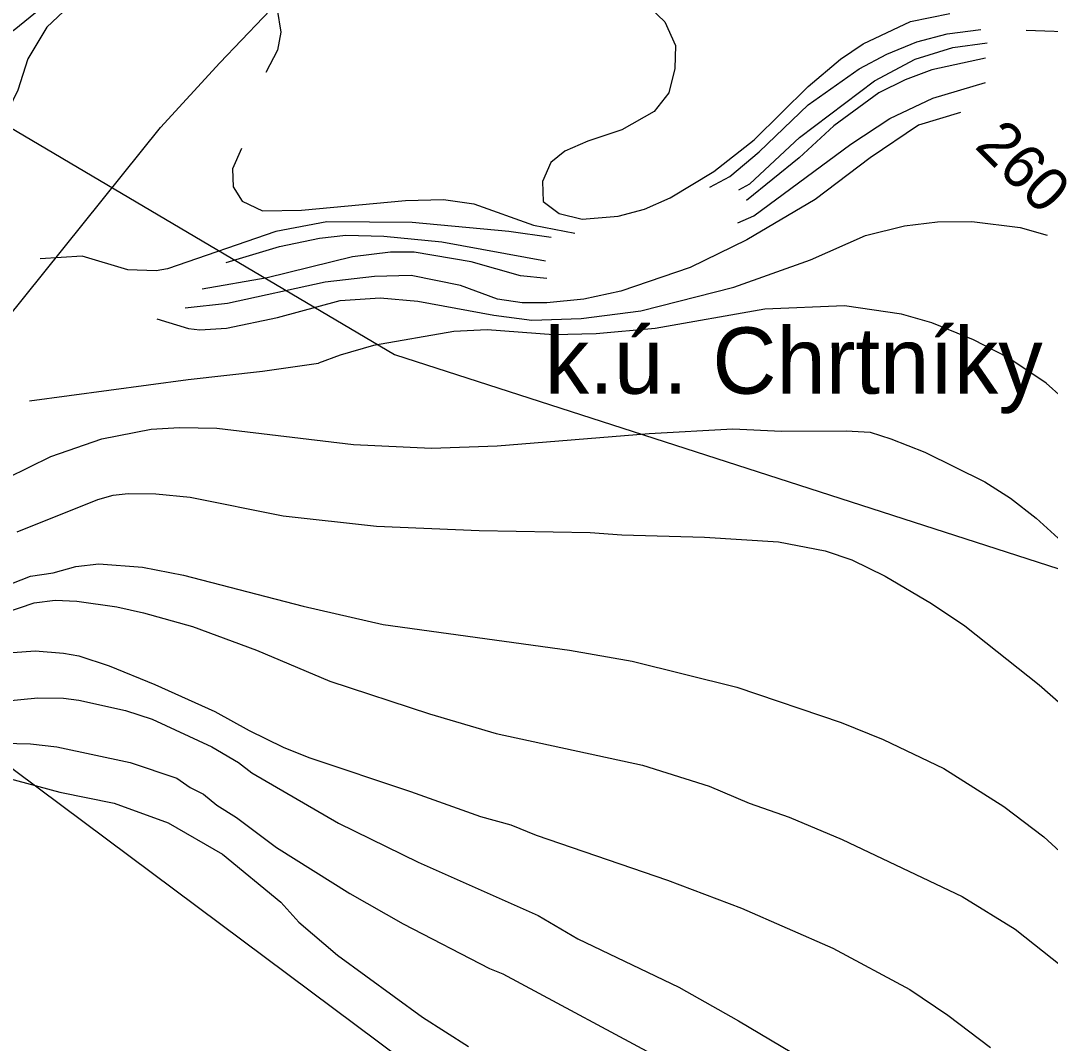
# Model space of a CAD drawing. Extents: x -662620 to -656370, y -1067090 to -1062990.
# Drawn here: x -660377.1 to -660066.6, y -1065930.1 to -1065621.6 of the extents above; entities that cross this region are included whole.
import ezdxf

# ---------------------------------------------------------------- set-up
doc = ezdxf.new("R2010")
doc.units = 0
for name, color, linetype in [('CHRANENE_LOZISKOVE_UZEMI', 7, 'Continuous'), ('NÁZEV_K__Ú_', 7, 'Continuous'), ('Ochr__pás__vod__zdroje_II__stupně', 7, 'Continuous'), ('SILNICE_II__TŘÍDY_A_III__TŘÍDY', 7, 'Continuous'), ('VRSTEVNICE_ZDŮRAZNĚNÁ', 7, 'Continuous'), ('VRSTEVNICE_ZDŮRAZNĚNÁ_-_POPIS', 7, 'Continuous'), ('VRSTEVNICE_ZÁKLADNÍ', 7, 'Continuous')]:
    doc.layers.add(name, color=color, linetype=linetype)

msp = doc.modelspace()

# ---------------------------------------------------------------- linework, layer by layer
at = {"layer": 'CHRANENE_LOZISKOVE_UZEMI'}
msp.add_lwpolyline([(-660732.31, -1065445.66), (-660264.34, -1065722.38), (-659885.89, -1065844.46), (-659943.47, -1066017.32)], dxfattribs=at)
at = {"layer": 'Ochr__pás__vod__zdroje_II__stupně'}
msp.add_lwpolyline([(-659772.42, -1066554.14), (-659800.07, -1066551.37), (-659811.95, -1066548.99), (-659926.01, -1066408.79), (-660023.43, -1066204.43), (-660077.21, -1066064.42), (-660108.05, -1066028.84), (-660146.01, -1066021.72), (-660474.51, -1065776.5), (-660482.87, -1065770.25), (-660599.12, -1065701.46), (-660658.43, -1065661.13), (-660656.42, -1065640.1), (-660662.94, -1065633.72), (-660669.94, -1065617.13), (-660675.36, -1065567.65)], dxfattribs=at)
at = {"layer": 'SILNICE_II__TŘÍDY_A_III__TŘÍDY'}
msp.add_lwpolyline([(-660468.75, -1065994.7), (-660462.97, -1065827.16), (-660446.28, -1065792.5), (-660334.88, -1065653.89), (-660317.01, -1065634.42), (-660277.86, -1065593.29), (-660232.35, -1065571.59), (-660040.54, -1065499.48), (-660012.53, -1065477.78), (-659990.24, -1065445.75), (-659930.63, -1065272.66), (-659916.62, -1065191.45)], dxfattribs=at)
at = {"layer": 'VRSTEVNICE_ZDŮRAZNĚNÁ'}
for points in [[(-660189.39, -1065615.74), (-660182.81, -1065622.03), (-660179.67, -1065629.18), (-660179.81, -1065636.04), (-660181.67, -1065643.47), (-660186.1, -1065649.05), (-660195.82, -1065654.62), (-660206.11, -1065658.05), (-660212.97, -1065661.05), (-660217.26, -1065664.48), (-660219.69, -1065670.2), (-660219.54, -1065676.2), (-660214.69, -1065679.78), (-660207.82, -1065681.49), (-660196.96, -1065680.63), (-660188.96, -1065678.49), (-660181.24, -1065675.06), (-660168.09, -1065667.2), (-660155.94, -1065657.62), (-660139.65, -1065641.47), (-660129.93, -1065633.32), (-660123.06, -1065628.61), (-660108.77, -1065621.89), (-660096.91, -1065619.46)], [(-660093.67, -1065649.31), (-660106.33, -1065653.19), (-660120.92, -1065663.05), (-660137.5, -1065675.63), (-660158.08, -1065687.78), (-660175.24, -1065696.07), (-660196.1, -1065703.22), (-660207.25, -1065705.65), (-660218.4, -1065706.79), (-660225.83, -1065706.79), (-660233.27, -1065705.65), (-660244.42, -1065701.5), (-660259.28, -1065698.5), (-660270.43, -1065698.79), (-660285.29, -1065700.5), (-660314.74, -1065706.93), (-660327.46, -1065708.36)], [(-660425.64, -1065809.51), (-660407.67, -1065801.78), (-660401.08, -1065799.78), (-660374.14, -1065789.17), (-660367.26, -1065788.17), (-660360.38, -1065786.3), (-660353.5, -1065785.44), (-660340.31, -1065786.45), (-660327.99, -1065788.88), (-660291.87, -1065798.2), (-660267.8, -1065803.79), (-660211.61, -1065811.53), (-660192.7, -1065814.83), (-660161.17, -1065822.71), (-660129.64, -1065833.31), (-660117.03, -1065838.47), (-660098.68, -1065847.21), (-660080.62, -1065858.68), (-660068.59, -1065867.85), (-660049.24, -1065885.48), (-660038.49, -1065898.81), (-660033.04, -1065907.26), (-660022.15, -1065929.05), (-660001.51, -1065962.01)], [(-660419.87, -1065848.7), (-660406.15, -1065849.41), (-660393.63, -1065848.65), (-660387.61, -1065848.79), (-660381.59, -1065849.94), (-660365.25, -1065854.38), (-660348.91, -1065857.68), (-660332.57, -1065863.55), (-660316.24, -1065873.01), (-660298.61, -1065887.49), (-660293.16, -1065893.51), (-660281.55, -1065903.54), (-660255.9, -1065922.17), (-660242, -1065931.05)]]:
    msp.add_lwpolyline(points, dxfattribs=at)
at = {"layer": 'VRSTEVNICE_ZÁKLADNÍ'}
for points in [[(-660440.08, -1065706.23), (-660427.51, -1065691.78), (-660420.22, -1065682.06), (-660417.08, -1065676.06), (-660417.08, -1065671.2), (-660421.79, -1065661.77), (-660422.22, -1065658.34), (-660420.08, -1065652.62), (-660417.94, -1065650.05), (-660413.08, -1065646.04), (-660379.06, -1065624.46), (-660366.19, -1065613.88), (-660331.75, -1065582.44), (-660320.17, -1065572.72), (-660298.46, -1065557.93), (-660282.72, -1065548.85), (-660243.27, -1065528.98), (-660222.4, -1065519.69), (-660195.25, -1065508.83), (-660183.81, -1065503.4), (-660176.24, -1065497.25), (-660175.29, -1065489.85)], [(-660440.08, -1065706.23), (-660427.51, -1065691.78), (-660420.22, -1065682.06), (-660417.08, -1065676.06), (-660417.08, -1065671.2), (-660421.79, -1065661.77), (-660422.22, -1065658.34), (-660420.08, -1065652.62), (-660417.94, -1065650.05), (-660413.08, -1065646.04), (-660379.06, -1065624.46), (-660366.19, -1065613.88), (-660331.75, -1065582.44), (-660320.17, -1065572.72), (-660298.46, -1065557.93), (-660282.72, -1065548.85), (-660243.27, -1065528.98), (-660222.4, -1065519.69), (-660195.25, -1065508.83), (-660183.81, -1065503.4), (-660176.24, -1065497.25), (-660175.29, -1065489.85)], [(-660159.71, -1065490.21), (-660160.08, -1065500.11), (-660166.95, -1065505.97), (-660171.09, -1065508.4), (-660188.24, -1065516.12), (-660207.54, -1065523.12), (-660234.12, -1065533.84), (-660269, -1065549.85), (-660292.44, -1065562.57), (-660306.45, -1065571.72), (-660322.74, -1065584.58), (-660335.18, -1065596.59), (-660362.48, -1065617.32), (-660369.2, -1065623.6), (-660374.91, -1065633.18), (-660377.91, -1065642.61), (-660382.49, -1065652.19), (-660388.63, -1065659.77), (-660397.64, -1065667.48), (-660406.36, -1065676.2), (-660416.08, -1065687.35), (-660423.64, -1065697.23), (-660429.13, -1065707.57)], [(-660159.71, -1065490.21), (-660160.08, -1065500.11), (-660166.95, -1065505.97), (-660171.09, -1065508.4), (-660188.24, -1065516.12), (-660207.54, -1065523.12), (-660234.12, -1065533.84), (-660269, -1065549.85), (-660292.44, -1065562.57), (-660306.45, -1065571.72), (-660322.74, -1065584.58), (-660335.18, -1065596.59), (-660362.48, -1065617.32), (-660369.2, -1065623.6), (-660374.91, -1065633.18), (-660377.91, -1065642.61), (-660382.49, -1065652.19), (-660388.63, -1065659.77), (-660397.64, -1065667.48), (-660406.36, -1065676.2), (-660416.08, -1065687.35), (-660423.64, -1065697.23), (-660429.13, -1065707.57)], [(-660181.24, -1065523.55), (-660216.4, -1065535.41), (-660243.84, -1065547.14), (-660259.28, -1065554.71), (-660271.29, -1065561.57), (-660302.16, -1065582.44), (-660307.16, -1065589.44), (-660308.16, -1065593.02), (-660308.3, -1065597.73), (-660305.02, -1065608.02), (-660299.73, -1065618.32), (-660298.59, -1065625.18), (-660299.59, -1065630.61), (-660303.16, -1065637.33)], [(-660181.24, -1065523.55), (-660216.4, -1065535.41), (-660243.84, -1065547.14), (-660259.28, -1065554.71), (-660271.29, -1065561.57), (-660302.16, -1065582.44), (-660307.16, -1065589.44), (-660308.16, -1065593.02), (-660308.3, -1065597.73), (-660305.02, -1065608.02), (-660299.73, -1065618.32), (-660298.59, -1065625.18), (-660299.59, -1065630.61), (-660303.16, -1065637.33)], [(-660073.95, -1065624.5), (-660056.89, -1065625.18), (-660046.88, -1065626.46), (-660037.73, -1065628.75), (-660032.02, -1065631.32), (-660020.87, -1065629.04), (-660016.58, -1065629.75), (-660007.43, -1065633.75), (-660000.86, -1065633.75), (-659994.85, -1065631.89), (-659986.28, -1065627.75), (-659980.28, -1065624.03), (-659975.13, -1065619.6)], [(-660073.95, -1065624.5), (-660056.89, -1065625.18), (-660046.88, -1065626.46), (-660037.73, -1065628.75), (-660032.02, -1065631.32), (-660020.87, -1065629.04), (-660016.58, -1065629.75), (-660007.43, -1065633.75), (-660000.86, -1065633.75), (-659994.85, -1065631.89), (-659986.28, -1065627.75), (-659980.28, -1065624.03), (-659975.13, -1065619.6)], [(-660169.23, -1065671.89), (-660163.23, -1065668.63), (-660154.37, -1065661.2), (-660139.65, -1065647.05), (-660124.21, -1065636.18), (-660115.92, -1065631.75), (-660106.91, -1065628.04), (-660097.76, -1065625.61), (-660087.62, -1065624.32)], [(-660169.23, -1065671.89), (-660163.23, -1065668.63), (-660154.37, -1065661.2), (-660139.65, -1065647.05), (-660124.21, -1065636.18), (-660115.92, -1065631.75), (-660106.91, -1065628.04), (-660097.76, -1065625.61), (-660087.62, -1065624.32)], [(-660160.51, -1065672.68), (-660157.23, -1065670.91), (-660142.22, -1065656.91), (-660119.63, -1065639.76), (-660107.34, -1065633.32), (-660096.05, -1065629.75), (-660085.62, -1065628.32)], [(-660160.51, -1065672.68), (-660157.23, -1065670.91), (-660142.22, -1065656.91), (-660119.63, -1065639.76), (-660107.34, -1065633.32), (-660096.05, -1065629.75), (-660085.62, -1065628.32)], [(-660086.21, -1065632.97), (-660102.34, -1065636.47), (-660110.34, -1065639.47), (-660118.35, -1065643.47), (-660131.93, -1065653.33), (-660142.36, -1065663.05), (-660158.23, -1065675.92)], [(-660086.21, -1065632.97), (-660102.34, -1065636.47), (-660110.34, -1065639.47), (-660118.35, -1065643.47), (-660131.93, -1065653.33), (-660142.36, -1065663.05), (-660158.23, -1065675.92)], [(-660160.8, -1065682.61), (-660156.05, -1065680.56), (-660126.78, -1065658.91), (-660115.06, -1065651.19), (-660102.05, -1065645.04), (-660086.19, -1065640.33)], [(-660160.8, -1065682.61), (-660156.05, -1065680.56), (-660126.78, -1065658.91), (-660115.06, -1065651.19), (-660102.05, -1065645.04), (-660086.19, -1065640.33)], [(-660310.49, -1065660.18), (-660313.17, -1065666.34), (-660313.02, -1065671.77), (-660310.31, -1065676.06), (-660304.16, -1065679.06), (-660292.44, -1065678.78), (-660261, -1065675.92), (-660249.56, -1065675.63), (-660240.41, -1065676.92), (-660222.4, -1065683.35), (-660209.97, -1065685.78)], [(-660310.49, -1065660.18), (-660313.17, -1065666.34), (-660313.02, -1065671.77), (-660310.31, -1065676.06), (-660304.16, -1065679.06), (-660292.44, -1065678.78), (-660261, -1065675.92), (-660249.56, -1065675.63), (-660240.41, -1065676.92), (-660222.4, -1065683.35), (-660209.97, -1065685.78)], [(-660217.1, -1065687.08), (-660229.84, -1065685.21), (-660258.99, -1065682.49), (-660284.72, -1065682.35), (-660300.16, -1065685.21), (-660332.75, -1065696.5), (-660336.18, -1065697.07), (-660344.75, -1065696.79), (-660358.48, -1065692.64), (-660371.2, -1065693.5)], [(-660217.1, -1065687.08), (-660229.84, -1065685.21), (-660258.99, -1065682.49), (-660284.72, -1065682.35), (-660300.16, -1065685.21), (-660332.75, -1065696.5), (-660336.18, -1065697.07), (-660344.75, -1065696.79), (-660358.48, -1065692.64), (-660371.2, -1065693.5)], [(-660335.98, -1065711.57), (-660326.46, -1065714.51), (-660323.03, -1065714.94), (-660315.02, -1065714.37), (-660299.59, -1065711.22), (-660280.72, -1065706.08), (-660268.71, -1065705.22), (-660257.28, -1065706.22), (-660234.41, -1065710.51), (-660222.97, -1065711.94), (-660208.11, -1065711.51), (-660190.1, -1065709.22), (-660162.09, -1065702.07), (-660138.93, -1065693.78), (-660122.35, -1065686.49), (-660110.63, -1065683.49), (-660100.62, -1065682.35), (-660090.33, -1065682.21), (-660075.75, -1065684.06), (-660067.61, -1065686.35)], [(-660335.98, -1065711.57), (-660326.46, -1065714.51), (-660323.03, -1065714.94), (-660315.02, -1065714.37), (-660299.59, -1065711.22), (-660280.72, -1065706.08), (-660268.71, -1065705.22), (-660257.28, -1065706.22), (-660234.41, -1065710.51), (-660222.97, -1065711.94), (-660208.11, -1065711.51), (-660190.1, -1065709.22), (-660162.09, -1065702.07), (-660138.93, -1065693.78), (-660122.35, -1065686.49), (-660110.63, -1065683.49), (-660100.62, -1065682.35), (-660090.33, -1065682.21), (-660075.75, -1065684.06), (-660067.61, -1065686.35)], [(-660315.14, -1065694.61), (-660299.01, -1065689.78), (-660287.01, -1065687.21), (-660279, -1065686.35), (-660267.57, -1065686.64), (-660250.13, -1065688.35), (-660218.83, -1065694.07)], [(-660315.14, -1065694.61), (-660299.01, -1065689.78), (-660287.01, -1065687.21), (-660279, -1065686.35), (-660267.57, -1065686.64), (-660250.13, -1065688.35), (-660218.83, -1065694.07)], [(-660218.43, -1065699.46), (-660226.4, -1065698.64), (-660241.27, -1065694.36), (-660258.42, -1065691.5), (-660265.57, -1065691.5), (-660277, -1065692.93), (-660302.73, -1065699.22), (-660322.31, -1065702.65)], [(-660218.43, -1065699.46), (-660226.4, -1065698.64), (-660241.27, -1065694.36), (-660258.42, -1065691.5), (-660265.57, -1065691.5), (-660277, -1065692.93), (-660302.73, -1065699.22), (-660322.31, -1065702.65)], [(-660046.52, -1065754.38), (-660054.03, -1065745.95), (-660063.18, -1065735.23), (-660067.89, -1065730.95), (-660079.47, -1065723.23), (-660089.76, -1065717.94), (-660102.34, -1065712.79), (-660111.49, -1065710.22), (-660128.64, -1065707.65), (-660152.65, -1065708.65), (-660185.81, -1065714.51), (-660203.54, -1065716.08), (-660216.4, -1065716.37), (-660236.41, -1065714.94), (-660246.42, -1065715.37), (-660270.71, -1065719.66), (-660280.72, -1065722.51), (-660287.25, -1065724.93)], [(-660046.52, -1065754.38), (-660054.03, -1065745.95), (-660063.18, -1065735.23), (-660067.89, -1065730.95), (-660079.47, -1065723.23), (-660089.76, -1065717.94), (-660102.34, -1065712.79), (-660111.49, -1065710.22), (-660128.64, -1065707.65), (-660152.65, -1065708.65), (-660185.81, -1065714.51), (-660203.54, -1065716.08), (-660216.4, -1065716.37), (-660236.41, -1065714.94), (-660246.42, -1065715.37), (-660270.71, -1065719.66), (-660280.72, -1065722.51), (-660287.25, -1065724.93)], [(-660374.44, -1065736.36), (-660326.56, -1065729.84), (-660304.2, -1065727.4), (-660287.25, -1065724.93)], [(-660374.44, -1065736.36), (-660326.56, -1065729.84), (-660304.2, -1065727.4), (-660287.25, -1065724.93)], [(-660394.2, -1065765.95), (-660367.97, -1065753.06), (-660352.64, -1065747.75), (-660337.73, -1065744.89), (-660329.13, -1065744.31), (-660317.96, -1065744.6), (-660276.68, -1065749.47), (-660253.18, -1065750.62), (-660233.4, -1065749.9), (-660187.54, -1065746.18), (-660162.31, -1065744.74), (-660147.7, -1065745.46), (-660128.2, -1065745.32), (-660120.9, -1065745.75), (-660114.73, -1065747.75), (-660104.41, -1065751.77), (-660086.36, -1065760.79), (-660078.62, -1065765.67), (-660070.88, -1065771.69), (-660063.14, -1065778.71)], [(-660394.2, -1065765.95), (-660367.97, -1065753.06), (-660352.64, -1065747.75), (-660337.73, -1065744.89), (-660329.13, -1065744.31), (-660317.96, -1065744.6), (-660276.68, -1065749.47), (-660253.18, -1065750.62), (-660233.4, -1065749.9), (-660187.54, -1065746.18), (-660162.31, -1065744.74), (-660147.7, -1065745.46), (-660128.2, -1065745.32), (-660120.9, -1065745.75), (-660114.73, -1065747.75), (-660104.41, -1065751.77), (-660086.36, -1065760.79), (-660078.62, -1065765.67), (-660070.88, -1065771.69), (-660063.14, -1065778.71)], [(-660378.15, -1065775.84), (-660353.79, -1065766.1), (-660349.2, -1065764.81), (-660344.61, -1065764.23), (-660336.3, -1065764.38), (-660325.98, -1065765.38), (-660297.89, -1065770.97), (-660269.8, -1065774.12), (-660238.84, -1065775.41), (-660205.31, -1065775.99), (-660195.85, -1065776.7), (-660170.91, -1065777.42), (-660148.56, -1065778.85), (-660134.51, -1065781.58), (-660126.49, -1065784.3), (-660116.45, -1065789.17), (-660102.41, -1065797.48), (-660092.38, -1065804.22), (-660070.02, -1065821.99), (-660059.99, -1065830.73)], [(-660378.15, -1065775.84), (-660353.79, -1065766.1), (-660349.2, -1065764.81), (-660344.61, -1065764.23), (-660336.3, -1065764.38), (-660325.98, -1065765.38), (-660297.89, -1065770.97), (-660269.8, -1065774.12), (-660238.84, -1065775.41), (-660205.31, -1065775.99), (-660195.85, -1065776.7), (-660170.91, -1065777.42), (-660148.56, -1065778.85), (-660134.51, -1065781.58), (-660126.49, -1065784.3), (-660116.45, -1065789.17), (-660102.41, -1065797.48), (-660092.38, -1065804.22), (-660070.02, -1065821.99), (-660059.99, -1065830.73)], [(-660389.9, -1065802.93), (-660372.99, -1065797.2), (-660366.68, -1065796.48), (-660360.09, -1065796.77), (-660348.05, -1065798.49), (-660340.03, -1065800.21), (-660325.26, -1065804.36), (-660305.92, -1065811.53), (-660283.85, -1065820.84), (-660253.75, -1065830.73), (-660233.69, -1065836.61), (-660189.54, -1065846.21), (-660169.48, -1065852.52), (-660157.44, -1065857.68), (-660145.4, -1065861.83), (-660129.35, -1065868.57), (-660093.24, -1065885.77), (-660077.18, -1065895.66), (-660063.14, -1065906.83), (-660055.11, -1065915.58), (-660045.08, -1065929.34), (-660028.17, -1065959.15)], [(-660389.9, -1065802.93), (-660372.99, -1065797.2), (-660366.68, -1065796.48), (-660360.09, -1065796.77), (-660348.05, -1065798.49), (-660340.03, -1065800.21), (-660325.26, -1065804.36), (-660305.92, -1065811.53), (-660283.85, -1065820.84), (-660253.75, -1065830.73), (-660233.69, -1065836.61), (-660189.54, -1065846.21), (-660169.48, -1065852.52), (-660157.44, -1065857.68), (-660145.4, -1065861.83), (-660129.35, -1065868.57), (-660093.24, -1065885.77), (-660077.18, -1065895.66), (-660063.14, -1065906.83), (-660055.11, -1065915.58), (-660045.08, -1065929.34), (-660028.17, -1065959.15)], [(-660431.91, -1065829.02), (-660418.71, -1065822.56), (-660401.08, -1065816.26), (-660391.62, -1065813.96), (-660382.16, -1065812.39), (-660372.7, -1065811.67), (-660364.1, -1065812.39), (-660359.52, -1065813.25), (-660350.35, -1065816.26), (-660336.59, -1065821.85), (-660318.53, -1065830.02), (-660308.21, -1065835.75), (-660297.89, -1065840.77), (-660290.15, -1065843.92), (-660259.48, -1065854.09), (-660238.41, -1065861.69), (-660229.24, -1065864.19), (-660221.65, -1065867.28), (-660182.09, -1065880.89), (-660159.73, -1065889.35), (-660132.22, -1065901.39), (-660109, -1065913.86), (-660097.54, -1065921.6), (-660084.64, -1065931.34)], [(-660431.91, -1065829.02), (-660418.71, -1065822.56), (-660401.08, -1065816.26), (-660391.62, -1065813.96), (-660382.16, -1065812.39), (-660372.7, -1065811.67), (-660364.1, -1065812.39), (-660359.52, -1065813.25), (-660350.35, -1065816.26), (-660336.59, -1065821.85), (-660318.53, -1065830.02), (-660308.21, -1065835.75), (-660297.89, -1065840.77), (-660290.15, -1065843.92), (-660259.48, -1065854.09), (-660238.41, -1065861.69), (-660229.24, -1065864.19), (-660221.65, -1065867.28), (-660182.09, -1065880.89), (-660159.73, -1065889.35), (-660132.22, -1065901.39), (-660109, -1065913.86), (-660097.54, -1065921.6), (-660084.64, -1065931.34)], [(-660439.22, -1065835.11), (-660434.24, -1065833.36), (-660428.15, -1065832.46), (-660418.28, -1065831.88), (-660387.32, -1065827.44), (-660371.84, -1065825.86), (-660364.1, -1065826), (-660359.52, -1065826.58), (-660345.47, -1065829.73), (-660337.45, -1065832.31), (-660319.39, -1065840.62), (-660311.36, -1065845.35), (-660307.35, -1065848.5), (-660281.27, -1065863.7), (-660257.19, -1065875.45), (-660221.07, -1065891.5), (-660209.04, -1065898.52), (-660178.65, -1065913.14), (-660160.59, -1065923.32), (-660128.49, -1065942.38)], [(-660439.22, -1065835.11), (-660434.24, -1065833.36), (-660428.15, -1065832.46), (-660418.28, -1065831.88), (-660387.32, -1065827.44), (-660371.84, -1065825.86), (-660364.1, -1065826), (-660359.52, -1065826.58), (-660345.47, -1065829.73), (-660337.45, -1065832.31), (-660319.39, -1065840.62), (-660311.36, -1065845.35), (-660307.35, -1065848.5), (-660281.27, -1065863.7), (-660257.19, -1065875.45), (-660221.07, -1065891.5), (-660209.04, -1065898.52), (-660178.65, -1065913.14), (-660160.59, -1065923.32), (-660128.49, -1065942.38)], [(-660435.81, -1065841.35), (-660430.93, -1065839.78), (-660423.15, -1065839.33), (-660412.54, -1065839.91), (-660386.46, -1065839.48), (-660374.14, -1065839.76), (-660366.11, -1065840.62), (-660344.04, -1065845.35), (-660329.99, -1065850.08), (-660325.98, -1065852.95), (-660321.97, -1065854.95), (-660317.96, -1065858.25), (-660311.94, -1065861.98), (-660299.9, -1065871), (-660277.83, -1065884.91), (-660261.78, -1065894.08), (-660235.69, -1065907.55), (-660231.68, -1065909.13), (-660181.52, -1065936.07)], [(-660435.81, -1065841.35), (-660430.93, -1065839.78), (-660423.15, -1065839.33), (-660412.54, -1065839.91), (-660386.46, -1065839.48), (-660374.14, -1065839.76), (-660366.11, -1065840.62), (-660344.04, -1065845.35), (-660329.99, -1065850.08), (-660325.98, -1065852.95), (-660321.97, -1065854.95), (-660317.96, -1065858.25), (-660311.94, -1065861.98), (-660299.9, -1065871), (-660277.83, -1065884.91), (-660261.78, -1065894.08), (-660235.69, -1065907.55), (-660231.68, -1065909.13), (-660181.52, -1065936.07)]]:
    msp.add_lwpolyline(points, dxfattribs=at)

# ---------------------------------------------------------------- texts
at = {"layer": 'NÁZEV_K__Ú_'}
msp.add_text('k.ú. Chrtníky', height=20, dxfattribs=at).set_placement((-660219.05, -1065734.17))
at = {"layer": 'VRSTEVNICE_ZDŮRAZNĚNÁ_-_POPIS'}
msp.add_text('260', height=13.2, rotation=314.9364, dxfattribs=at).set_placement((-660089.74, -1065659.76))

doc.saveas('drawing.dxf')
